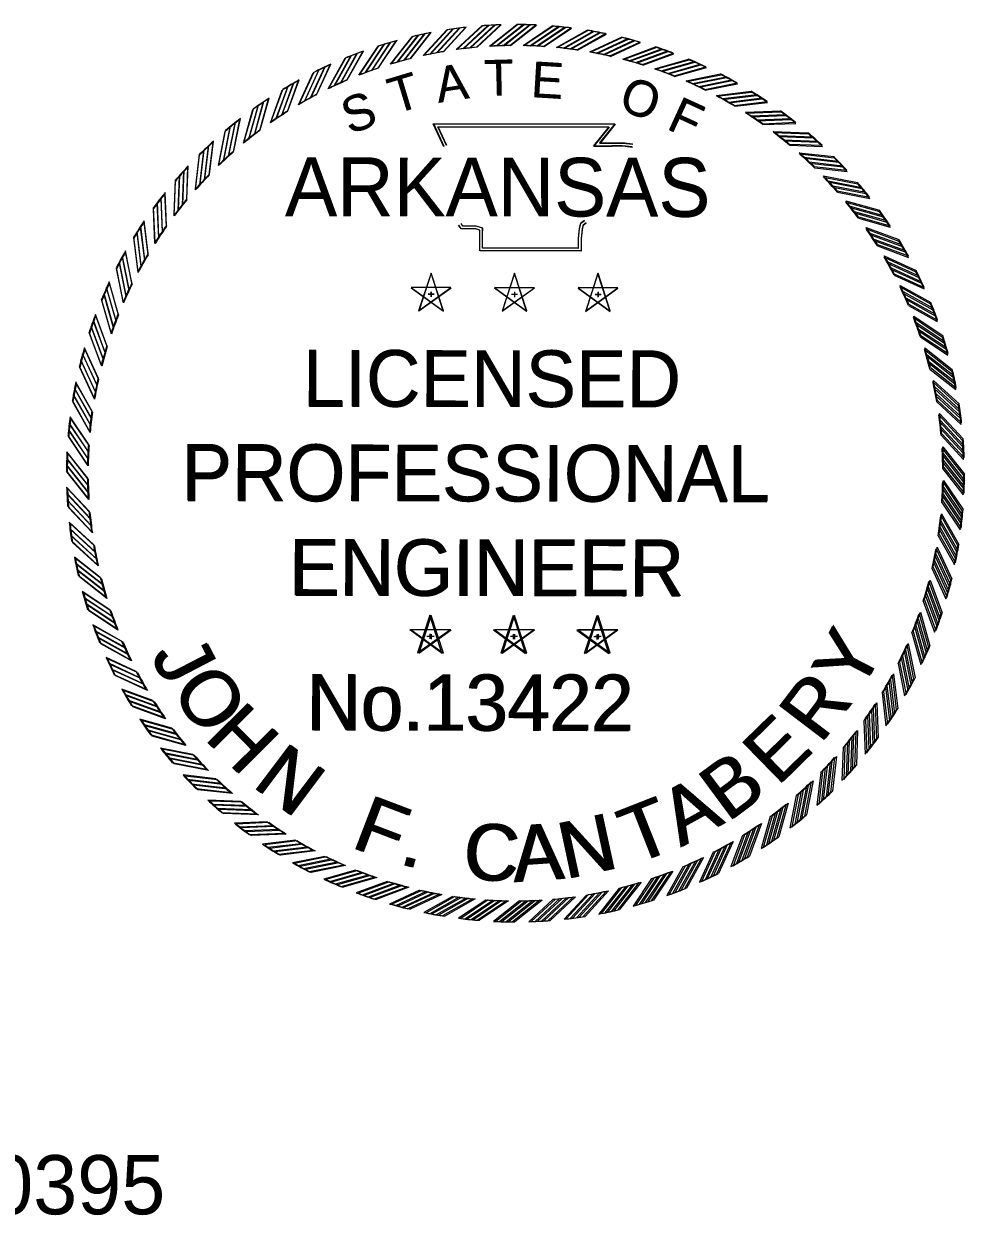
# Model space of a CAD drawing. Extents: x 1373884 to 1377798, y 1168424 to 1170626.
# Drawn here: x 1377543.4 to 1377797.8, y 1168462.5 to 1168784.5 of the extents above; entities that cross this region are included whole.
import ezdxf

# ---------------------------------------------------------------- set-up
doc = ezdxf.new("R2010")
doc.units = 0
doc.layers.add('2', color=7, linetype='Continuous')
doc.layers.add('Default', color=7, linetype='Continuous')

# ---------------------------------------------------------------- blocks, each defined once
blk = doc.blocks.new('STAR')
at = {"layer": 'Default'}
for p, q in [((-0.0001, 0.0615), (-0.0366, -0.0504)), ((0.0362, -0.0503), (0, 0.0617)), ((0.0587, 0.0188), (-0.059, 0.0189)), ((-0.0589, 0.0188), (0.0363, -0.0505)), ((-0.0365, -0.0503), (0.0589, 0.0188)), ((-0.0085, 0), (0.009, 0)), ((0, 0.0063), (0, -0.0085))]:
    blk.add_line(p, q, dxfattribs=at)
blk = doc.blocks.new('RP')
at = {"layer": 'Default'}
for p, q in [((-0.0781, 1.2656), (0.003, 1.33)), ((-0.058, 1.2667), (0.0216, 1.3299)), ((-0.0375, 1.2674), (0.0405, 1.3294)), ((-0.0176, 1.2679), (0.059, 1.3287))]:
    blk.add_line(p, q, dxfattribs=at)
for radius, start, end in [(1.33, 87.4562, 89.8699), (1.268, 90.7933, 93.5307)]:
    blk.add_arc((0, 0), radius, start, end, dxfattribs=at)

msp = doc.modelspace()

# ---------------------------------------------------------------- linework, layer by layer
at = {"layer": 'Default'}
for points in [[(1377656.89, 1168751.27), (1377654.05, 1168757.41), (1377703.09, 1168757.43), (1377699, 1168752.29), (1377702.33, 1168752.33), (1377705.11, 1168752.37), (1377707.89, 1168752.06)], [(1377656.98, 1168751.3), (1377654.17, 1168757.45), (1377703.21, 1168757.31), (1377699.1, 1168752.17), (1377702.43, 1168752.21), (1377705.21, 1168752.23), (1377707.99, 1168751.92)], [(1377657.59, 1168751.59), (1377655.27, 1168756.63), (1377701.48, 1168756.66), (1377697.37, 1168751.49), (1377702.34, 1168751.55), (1377705.07, 1168751.59), (1377707.81, 1168751.29)], [(1377657.69, 1168751.62), (1377655.38, 1168756.67), (1377701.6, 1168756.54), (1377697.47, 1168751.38), (1377702.44, 1168751.43), (1377705.17, 1168751.46), (1377707.9, 1168751.15)], [(1377695.37, 1168730.72), (1377694.53, 1168730.04), (1377694.25, 1168729.02), (1377693.98, 1168726.48), (1377693.98, 1168723.09), (1377666.6, 1168723.09), (1377666.6, 1168727.66), (1377666.6, 1168728.68), (1377665.49, 1168729.02), (1377661.59, 1168729.02), (1377660.9, 1168730.07)], [(1377695.39, 1168730.62), (1377694.55, 1168729.94), (1377694.27, 1168728.92), (1377693.99, 1168726.38), (1377693.98, 1168722.99), (1377666.6, 1168723.09), (1377666.61, 1168727.66), (1377666.62, 1168728.68), (1377665.51, 1168729.02), (1377661.61, 1168729.04), (1377660.93, 1168730.09)], [(1377694.88, 1168731.32), (1377693.85, 1168730.48), (1377693.49, 1168729.16), (1377693.2, 1168726.52), (1377693.2, 1168723.86), (1377667.38, 1168723.86), (1377667.38, 1168727.66), (1377667.38, 1168729.25), (1377665.6, 1168729.79), (1377662.01, 1168729.79), (1377661.55, 1168730.5)], [(1377694.9, 1168731.22), (1377693.87, 1168730.39), (1377693.51, 1168729.07), (1377693.21, 1168726.43), (1377693.2, 1168723.77), (1377667.38, 1168723.86), (1377667.39, 1168727.66), (1377667.4, 1168729.25), (1377665.63, 1168729.8), (1377662.04, 1168729.81), (1377661.58, 1168730.52)]]:
    msp.add_lwpolyline(points, dxfattribs=at)

# ---------------------------------------------------------------- block references
for name, p, xscale, yscale, rotation in [('RP', (1377676.37, 1168663.02), 91.17655343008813, 91.17655343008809, 13.500000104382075), ('RP', (1377676.16, 1168662.99), 91.17655343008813, 91.17655343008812, 13.304199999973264), ('RP', (1377676.37, 1168663.02), 91.17655343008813, 91.17655343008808, 9.000000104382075), ('RP', (1377676.16, 1168662.99), 91.17655343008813, 91.17655343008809, 8.804199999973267), ('RP', (1377676.37, 1168663.02), 91.17655343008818, 91.17655343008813, 4.500000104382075), ('RP', (1377676.16, 1168662.99), 91.17655343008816, 91.17655343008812, 4.304199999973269), ('RP', (1377676.37, 1168663.02), 91.17655343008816, 91.17655343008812, 1.0438208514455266e-07), ('RP', (1377676.16, 1168662.99), 91.17655343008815, 91.1765534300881, -0.19580000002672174), ('RP', (1377676.37, 1168663.02), 91.17655343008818, 91.17655343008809, -4.499999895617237), ('RP', (1377676.16, 1168662.99), 91.17655343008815, 91.17655343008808, -4.695800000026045), ('RP', (1377676.37, 1168663.02), 91.17655343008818, 91.17655343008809, -8.999999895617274), ('RP', (1377676.16, 1168662.99), 91.17655343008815, 91.17655343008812, -9.195800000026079), ('RP', (1377676.37, 1168663.02), 91.17655343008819, 91.17655343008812, -13.499999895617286), ('RP', (1377676.16, 1168662.99), 91.17655343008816, 91.17655343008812, -13.695800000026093), ('RP', (1377676.37, 1168663.02), 91.17655343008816, 91.1765534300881, 18.00000010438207), ('RP', (1377676.16, 1168662.99), 91.17655343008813, 91.17655343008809, 17.80419999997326), ('RP', (1377676.37, 1168663.02), 91.17655343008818, 91.1765534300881, -17.99999989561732), ('RP', (1377676.16, 1168662.99), 91.17655343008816, 91.1765534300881, -18.195800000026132), ('RP', (1377676.37, 1168663.02), 91.17655343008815, 91.17655343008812, 22.50000010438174), ('RP', (1377676.16, 1168662.99), 91.17655343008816, 91.1765534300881, 22.304199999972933), ('RP', (1377676.37, 1168663.02), 91.17655343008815, 91.17655343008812, -22.499999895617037), ('RP', (1377676.16, 1168662.99), 91.17655343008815, 91.17655343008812, -22.695800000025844), ('RP', (1377676.37, 1168663.02), 91.17655343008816, 91.17655343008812, 27.00000010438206), ('RP', (1377676.16, 1168662.99), 91.17655343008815, 91.17655343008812, 26.80419999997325), ('RP', (1377676.37, 1168663.02), 91.17655343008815, 91.1765534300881, -26.999999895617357), ('RP', (1377676.16, 1168662.99), 91.17655343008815, 91.17655343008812, -27.19580000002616), ('RP', (1377676.37, 1168663.02), 91.1765534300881, 91.17655343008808, 31.500000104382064), ('RP', (1377676.16, 1168662.99), 91.17655343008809, 91.17655343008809, 31.30419999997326), ('RP', (1377676.37, 1168663.02), 91.17655343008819, 91.17655343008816, -31.49999989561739), ('RP', (1377676.16, 1168662.99), 91.17655343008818, 91.17655343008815, -31.695800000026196), ('RP', (1377676.37, 1168663.02), 91.17655343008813, 91.17655343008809, 36.000000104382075), ('RP', (1377676.16, 1168662.99), 91.17655343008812, 91.1765534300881, 35.804199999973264), ('RP', (1377676.37, 1168663.02), 91.17655343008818, 91.17655343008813, -35.99999989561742), ('RP', (1377676.16, 1168662.99), 91.17655343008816, 91.17655343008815, -36.19580000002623), ('RP', (1377676.37, 1168663.02), 91.17655343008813, 91.17655343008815, -40.49999989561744), ('RP', (1377676.16, 1168662.99), 91.17655343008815, 91.17655343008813, -40.69580000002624), ('RP', (1377676.37, 1168663.02), 91.17655343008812, 91.17655343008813, 40.50000010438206), ('RP', (1377676.16, 1168662.99), 91.17655343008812, 91.1765534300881, 40.30419999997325), ('RP', (1377676.16, 1168662.99), 91.1765534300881, 91.17655343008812, 44.80419999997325), ('RP', (1377676.37, 1168663.02), 91.17655343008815, 91.17655343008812, -44.99999989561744), ('RP', (1377676.16, 1168662.99), 91.17655343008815, 91.1765534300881, -45.19580000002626), ('RP', (1377676.37, 1168663.02), 91.17655343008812, 91.17655343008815, 45.00000010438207), ('RP', (1377676.37, 1168663.02), 91.17655343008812, 91.17655343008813, -49.49999989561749), ('RP', (1377676.16, 1168662.99), 91.1765534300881, 91.1765534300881, -49.69580000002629), ('RP', (1377676.37, 1168663.02), 91.17655343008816, 91.17655343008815, 49.50000010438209), ('RP', (1377676.16, 1168662.99), 91.17655343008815, 91.17655343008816, 49.304199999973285), ('RP', (1377676.37, 1168663.02), 91.17655343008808, 91.1765534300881, -53.999999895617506), ('RP', (1377676.37, 1168663.02), 91.17655343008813, 91.17655343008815, 54.00000010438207), ('RP', (1377676.16, 1168662.99), 91.17655343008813, 91.17655343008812, 53.80419999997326), ('RP', (1377676.16, 1168662.99), 91.17655343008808, 91.17655343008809, -54.1958000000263), ('RP', (1377676.16, 1168662.99), 91.1765534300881, 91.17655343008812, 58.304199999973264), ('RP', (1377676.37, 1168663.02), 91.1765534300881, 91.17655343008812, 58.50000010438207), ('RP', (1377676.37, 1168663.02), 91.1765534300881, 91.17655343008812, -58.49999989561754), ('RP', (1377676.16, 1168662.99), 91.1765534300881, 91.1765534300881, -58.695800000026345), ('RP', (1377676.16, 1168662.99), 91.17655343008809, 91.17655343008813, -63.19580000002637), ('RP', (1377676.37, 1168663.02), 91.17655343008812, 91.17655343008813, -62.99999989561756), ('RP', (1377676.16, 1168662.99), 91.17655343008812, 91.17655343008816, 62.804199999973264), ('RP', (1377676.37, 1168663.02), 91.17655343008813, 91.17655343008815, 63.000000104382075), ('RP', (1377676.16, 1168662.99), 91.1765534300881, 91.17655343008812, 67.30419999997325), ('RP', (1377676.37, 1168663.02), 91.17655343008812, 91.17655343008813, 67.50000010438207), ('STAR', (1377653.43, 1168711.48), 91.17655343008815, 91.1765534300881, -0.19580000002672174), ('STAR', (1377653.47, 1168711.44), 91.17655343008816, 91.17655343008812, 1.0438208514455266e-07), ('STAR', (1377675.99, 1168711.41), 91.17655343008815, 91.1765534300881, -0.19580000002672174), ('STAR', (1377676.03, 1168711.44), 91.17655343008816, 91.17655343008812, 1.0438208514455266e-07), ('STAR', (1377698.54, 1168711.33), 91.17655343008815, 91.1765534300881, -0.19580000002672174), ('STAR', (1377698.58, 1168711.44), 91.17655343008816, 91.17655343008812, 1.0438208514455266e-07), ('RP', (1377676.16, 1168662.99), 91.17655343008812, 91.17655343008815, -67.69580000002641), ('RP', (1377676.37, 1168663.02), 91.1765534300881, 91.17655343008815, -67.49999989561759), ('RP', (1377676.16, 1168662.99), 91.17655343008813, 91.17655343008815, 71.80419999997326), ('RP', (1377676.37, 1168663.02), 91.1765534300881, 91.17655343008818, 72.00000010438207), ('RP', (1377676.16, 1168662.99), 91.17655343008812, 91.17655343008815, -72.19580000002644), ('RP', (1377676.37, 1168663.02), 91.17655343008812, 91.17655343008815, -71.99999989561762), ('RP', (1377676.37, 1168663.02), 91.17655343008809, 91.17655343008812, -76.49999989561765), ('RP', (1377676.16, 1168662.99), 91.17655343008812, 91.17655343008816, 76.30419999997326), ('RP', (1377676.37, 1168663.02), 91.17655343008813, 91.17655343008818, 76.50000010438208), ('RP', (1377676.16, 1168662.99), 91.17655343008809, 91.17655343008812, -76.69580000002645), ('RP', (1377676.16, 1168662.99), 91.1765534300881, 91.17655343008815, -81.19580000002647), ('RP', (1377676.37, 1168663.02), 91.17655343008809, 91.17655343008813, -80.99999989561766), ('RP', (1377676.16, 1168662.99), 91.17655343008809, 91.17655343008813, 80.80419999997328), ('RP', (1377676.37, 1168663.02), 91.1765534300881, 91.17655343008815, 81.0000001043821), ('RP', (1377676.16, 1168662.99), 91.17655343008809, 91.17655343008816, -85.69580000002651), ('RP', (1377676.37, 1168663.02), 91.1765534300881, 91.17655343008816, -85.49999989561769), ('RP', (1377676.16, 1168662.99), 91.1765534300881, 91.17655343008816, 85.30419999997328), ('RP', (1377676.37, 1168663.02), 91.17655343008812, 91.17655343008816, 85.50000010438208), ('RP', (1377676.16, 1168662.99), 91.17655343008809, 91.17655343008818, -90.19580000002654), ('RP', (1377676.37, 1168663.02), 91.17655343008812, 91.17655343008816, -89.99999989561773), ('RP', (1377676.16, 1168662.99), 91.1765534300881, 91.17655343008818, 89.80419999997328), ('RP', (1377676.37, 1168663.02), 91.17655343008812, 91.17655343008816, 90.0000001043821), ('RP', (1377676.16, 1168662.99), 91.1765534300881, 91.1765534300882, 94.30419999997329), ('RP', (1377676.37, 1168663.02), 91.17655343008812, 91.17655343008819, 94.5000001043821), ('RP', (1377676.16, 1168662.99), 91.1765534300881, 91.17655343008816, -94.69580000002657), ('RP', (1377676.37, 1168663.02), 91.17655343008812, 91.17655343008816, -94.49999989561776), ('RP', (1377676.16, 1168662.99), 91.1765534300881, 91.17655343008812, 98.8041999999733), ('RP', (1377676.37, 1168663.02), 91.17655343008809, 91.17655343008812, 99.0000001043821), ('RP', (1377676.16, 1168662.99), 91.1765534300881, 91.17655343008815, -99.19580000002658), ('RP', (1377676.37, 1168663.02), 91.17655343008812, 91.17655343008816, -98.99999989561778), ('RP', (1377676.16, 1168662.99), 91.1765534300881, 91.17655343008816, 103.30419999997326), ('RP', (1377676.37, 1168663.02), 91.1765534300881, 91.17655343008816, 103.50000010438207), ('RP', (1377676.16, 1168662.99), 91.17655343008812, 91.17655343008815, -103.69580000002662), ('RP', (1377676.37, 1168663.02), 91.1765534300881, 91.17655343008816, -103.49999989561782), ('RP', (1377676.16, 1168662.99), 91.1765534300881, 91.17655343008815, -108.19580000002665), ('RP', (1377676.37, 1168663.02), 91.17655343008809, 91.17655343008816, -107.99999989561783), ('RP', (1377676.16, 1168662.99), 91.17655343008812, 91.17655343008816, 107.80419999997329), ('RP', (1377676.37, 1168663.02), 91.17655343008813, 91.17655343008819, 108.0000001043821), ('RP', (1377676.16, 1168662.99), 91.1765534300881, 91.17655343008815, 112.30419999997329), ('STAR', (1377653.12, 1168619), 91.17655343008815, 91.1765534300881, -0.19580000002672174), ('STAR', (1377653.47, 1168618.96), 91.17655343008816, 91.17655343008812, 1.0438208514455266e-07), ('STAR', (1377675.67, 1168618.93), 91.17655343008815, 91.1765534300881, -0.19580000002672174), ('STAR', (1377676.03, 1168618.96), 91.17655343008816, 91.17655343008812, 1.0438208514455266e-07), ('STAR', (1377698.23, 1168618.85), 91.17655343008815, 91.1765534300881, -0.19580000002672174), ('STAR', (1377698.58, 1168618.96), 91.17655343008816, 91.17655343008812, 1.0438208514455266e-07), ('RP', (1377676.16, 1168662.99), 91.1765534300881, 91.17655343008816, -112.69580000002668), ('RP', (1377676.37, 1168663.02), 91.1765534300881, 91.17655343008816, -112.49999989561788), ('RP', (1377676.37, 1168663.02), 91.1765534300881, 91.17655343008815, 112.5000001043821), ('RP', (1377676.16, 1168662.99), 91.17655343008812, 91.17655343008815, 116.80419999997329), ('RP', (1377676.37, 1168663.02), 91.17655343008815, 91.17655343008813, 117.0000001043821), ('RP', (1377676.16, 1168662.99), 91.17655343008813, 91.17655343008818, -117.19580000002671), ('RP', (1377676.37, 1168663.02), 91.17655343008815, 91.17655343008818, -116.9999998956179), ('RP', (1377676.16, 1168662.99), 91.17655343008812, 91.17655343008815, -121.69580000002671), ('RP', (1377676.37, 1168663.02), 91.17655343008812, 91.17655343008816, -121.4999998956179), ('RP', (1377676.16, 1168662.99), 91.17655343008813, 91.17655343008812, 121.30419999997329), ('RP', (1377676.37, 1168663.02), 91.17655343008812, 91.17655343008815, 121.5000001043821), ('RP', (1377676.16, 1168662.99), 91.17655343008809, 91.17655343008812, 125.80419999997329), ('RP', (1377676.37, 1168663.02), 91.17655343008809, 91.17655343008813, 126.00000010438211), ('RP', (1377676.16, 1168662.99), 91.17655343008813, 91.17655343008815, -126.19580000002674), ('RP', (1377676.37, 1168663.02), 91.17655343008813, 91.17655343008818, -125.99999989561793), ('RP', (1377676.16, 1168662.99), 91.1765534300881, 91.17655343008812, 130.3041999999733), ('RP', (1377676.37, 1168663.02), 91.17655343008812, 91.17655343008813, 130.50000010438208), ('RP', (1377676.16, 1168662.99), 91.17655343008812, 91.17655343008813, -130.6958000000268), ('RP', (1377676.37, 1168663.02), 91.17655343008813, 91.17655343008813, -130.49999989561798), ('RP', (1377676.16, 1168662.99), 91.17655343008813, 91.17655343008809, 134.8041999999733), ('RP', (1377676.37, 1168663.02), 91.17655343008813, 91.17655343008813, 135.0000001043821), ('RP', (1377676.16, 1168662.99), 91.1765534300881, 91.17655343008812, -135.19580000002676), ('RP', (1377676.37, 1168663.02), 91.17655343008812, 91.17655343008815, -134.99999989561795), ('RP', (1377676.16, 1168662.99), 91.17655343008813, 91.17655343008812, 139.30419999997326), ('RP', (1377676.37, 1168663.02), 91.17655343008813, 91.17655343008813, 139.50000010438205), ('RP', (1377676.16, 1168662.99), 91.1765534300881, 91.17655343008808, -139.69580000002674), ('RP', (1377676.37, 1168663.02), 91.17655343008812, 91.17655343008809, -139.49999989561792), ('RP', (1377676.16, 1168662.99), 91.17655343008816, 91.17655343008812, 143.8041999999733), ('RP', (1377676.37, 1168663.02), 91.17655343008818, 91.17655343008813, 144.00000010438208), ('RP', (1377676.16, 1168662.99), 91.17655343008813, 91.17655343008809, -144.19580000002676), ('RP', (1377676.37, 1168663.02), 91.17655343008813, 91.17655343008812, -143.99999989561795), ('RP', (1377676.16, 1168662.99), 91.17655343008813, 91.17655343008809, 148.3041999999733), ('RP', (1377676.37, 1168663.02), 91.17655343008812, 91.1765534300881, 148.50000010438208), ('RP', (1377676.16, 1168662.99), 91.17655343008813, 91.17655343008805, -148.69580000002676), ('RP', (1377676.37, 1168663.02), 91.17655343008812, 91.1765534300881, -148.49999989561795), ('RP', (1377676.16, 1168662.99), 91.17655343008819, 91.17655343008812, 152.8041999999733), ('RP', (1377676.16, 1168662.99), 91.17655343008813, 91.17655343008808, -153.1958000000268), ('RP', (1377676.37, 1168663.02), 91.17655343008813, 91.17655343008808, -152.99999989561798), ('RP', (1377676.37, 1168663.02), 91.17655343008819, 91.17655343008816, 153.00000010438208), ('RP', (1377676.16, 1168662.99), 91.17655343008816, 91.17655343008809, 157.3041999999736), ('RP', (1377676.37, 1168663.02), 91.17655343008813, 91.17655343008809, 157.50000010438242), ('RP', (1377676.16, 1168662.99), 91.17655343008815, 91.17655343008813, -157.6958000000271), ('RP', (1377676.37, 1168663.02), 91.17655343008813, 91.17655343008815, -157.4999998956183), ('RP', (1377676.16, 1168662.99), 91.17655343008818, 91.1765534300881, 161.8041999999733), ('RP', (1377676.37, 1168663.02), 91.1765534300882, 91.17655343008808, 162.00000010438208), ('RP', (1377676.16, 1168662.99), 91.17655343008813, 91.17655343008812, -162.19580000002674), ('RP', (1377676.37, 1168663.02), 91.17655343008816, 91.17655343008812, -161.99999989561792), ('RP', (1377676.16, 1168662.99), 91.17655343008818, 91.17655343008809, 166.3041999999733), ('RP', (1377676.37, 1168663.02), 91.17655343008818, 91.17655343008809, 166.50000010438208), ('RP', (1377676.16, 1168662.99), 91.17655343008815, 91.17655343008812, 170.8041999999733), ('RP', (1377676.37, 1168663.02), 91.17655343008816, 91.1765534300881, 171.00000010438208), ('RP', (1377676.16, 1168662.99), 91.1765534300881, 91.1765534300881, -171.19580000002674), ('RP', (1377676.37, 1168663.02), 91.17655343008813, 91.17655343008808, -170.99999989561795), ('RP', (1377676.16, 1168662.99), 91.17655343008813, 91.17655343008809, -166.69580000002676), ('RP', (1377676.37, 1168663.02), 91.17655343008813, 91.17655343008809, -166.49999989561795), ('RP', (1377676.16, 1168662.99), 91.17655343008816, 91.1765534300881, 175.3041999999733), ('RP', (1377676.37, 1168663.02), 91.17655343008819, 91.17655343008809, 175.50000010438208), ('RP', (1377676.16, 1168662.99), 91.17655343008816, 91.17655343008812, 179.8041999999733), ('RP', (1377676.37, 1168663.02), 91.17655343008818, 91.1765534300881, -179.99999989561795), ('RP', (1377676.16, 1168662.99), 91.17655343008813, 91.17655343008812, -175.69580000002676), ('RP', (1377676.37, 1168663.02), 91.17655343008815, 91.17655343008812, -175.49999989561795)]:
    msp.add_blockref(name, p, dxfattribs=dict(at, xscale=xscale, yscale=yscale, rotation=rotation))

# ---------------------------------------------------------------- texts
at = {"layer": '2'}
msp.add_text('P.E. JOB 060395', height=16, dxfattribs=at).set_placement((1377416.28, 1168462.68))
at = {"layer": 'Default'}
for s, height, rotation, p in [('A', 9.67, 8.6788, (1377655.39, 1168763.07)), ('A', 9.67, 8.483, (1377655.53, 1168763.11)), ('T', 9.67, 1.4789, (1377667.89, 1168765)), ('T', 9.67, 1.2831, (1377668.03, 1168764.99)), ('E', 9.67, 356.672, (1377680.27, 1168764.7)), ('E', 9.67, 356.4762, (1377680.41, 1168764.66)), ('T', 9.67, 16.9015, (1377643.65, 1168760.01)), ('T', 9.67, 16.7057, (1377643.77, 1168760.08)), ('O', 9.67, 341.2218, (1377703.75, 1168761.39)), ('O', 9.67, 341.026, (1377703.88, 1168761.26)), ('S', 9.67, 19.7726, (1377631.35, 1168754.48)), ('S', 9.67, 19.5768, (1377631.45, 1168754.6)), ('F', 9.67, 335.3628, (1377716.79, 1168756.29)), ('F', 9.67, 335.167, (1377716.9, 1168756.12)), ('ARKANSAS', 15.788, 359.8042, (1377614, 1168732.66)), ('LICENSED', 15.285, 359.8042, (1377618.72, 1168681.11)), ('PROFESSIONAL', 15.2848, 359.8042, (1377585.88, 1168655.66)), ('ENGINEER', 15.285, 359.8042, (1377614.91, 1168629.99)), ('Y', 15.28, 62.5392, (1377769.34, 1168603)), ('Y', 15.28, 62.735, (1377769.75, 1168603.36)), ('J', 15.28, 297.2813, (1377577.36, 1168613.86)), ('J', 15.28, 297.4771, (1377577.74, 1168613.56)), ('O', 15.28, 304.1899, (1377582.78, 1168604.49)), ('O', 15.28, 304.3857, (1377583.18, 1168604.2)), ('No.13422', 15.225, 359.8042, (1377619.61, 1168593.54)), ('R', 15.28, 52.7437, (1377758.67, 1168589.54)), ('R', 15.28, 52.9395, (1377759.12, 1168589.86)), ('H', 15.28, 314.7447, (1377591.79, 1168591.32)), ('H', 15.28, 314.9405, (1377592.24, 1168591.07)), ('E', 15.28, 44.306, (1377747.02, 1168578.17)), ('E', 15.28, 44.5018, (1377747.52, 1168578.44)), ('N', 15.28, 322.9417, (1377604.7, 1168578.54)), ('N', 15.28, 323.1375, (1377605.19, 1168578.33)), ('B', 15.28, 36.505, (1377733.54, 1168568.44)), ('B', 15.28, 36.7008, (1377734.06, 1168568.67)), ('A', 15.28, 28.8562, (1377720.84, 1168561.77)), ('A', 15.28, 29.052, (1377721.39, 1168561.96)), ('F', 15.28, 339.0288, (1377631.38, 1168561.99)), ('F', 15.28, 339.2246, (1377631.93, 1168561.87)), ('T', 15.28, 21.4329, (1377708.13, 1168556.99)), ('T', 15.28, 21.6287, (1377708.7, 1168557.13)), ('N', 15.28, 12.0703, (1377689.69, 1168553.18)), ('N', 15.28, 12.2661, (1377690.27, 1168553.26)), ('C', 15.28, 356.1028, (1377661.7, 1168553.41)), ('C', 15.28, 356.2986, (1377662.28, 1168553.39)), ('A', 15.28, 3.9092, (1377675.72, 1168552.4)), ('A', 15.28, 4.105, (1377676.31, 1168552.43)), ('.', 15.28, 344.7037, (1377644.42, 1168557.47)), ('.', 15.28, 344.8995, (1377644.98, 1168557.39))]:
    msp.add_text(s, height=height, rotation=rotation, dxfattribs=at).set_placement(p)
for s, height, p in [('ARKANSAS', 15.788, (1377613.96, 1168732.48)), ('LICENSED', 15.285, (1377618.87, 1168680.94)), ('PROFESSIONAL', 15.2848, (1377586.11, 1168655.38)), ('ENGINEER', 15.285, (1377615.23, 1168629.82)), ('No.13422', 15.225, (1377620.05, 1168593.38))]:
    msp.add_text(s, height=height, dxfattribs=at).set_placement(p)

doc.saveas('drawing.dxf')
